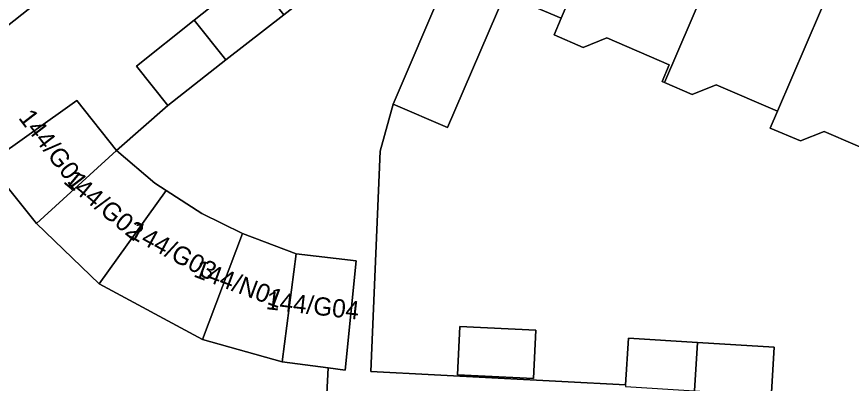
# Model space of a CAD drawing. Extents: x 162073 to 163043, y 381818 to 382561.
# Drawn here: x 162373.02 to 162418.89, y 382500.88 to 382521.02 of the extents above; entities that cross this region are included whole.
import ezdxf

# ---------------------------------------------------------------- set-up
doc = ezdxf.new("R2010")
doc.units = 0
for name, color, linetype in [('IMGEO_Erf', 7, 'Continuous'), ('IMGEO_Pand', 7, 'Continuous'), ('IMGEO_Pand_nummerreeks', 7, 'Continuous'), ('IMGEO_Voetpad_open', 7, 'Continuous')]:
    doc.layers.add(name, color=color, linetype=linetype)

msp = doc.modelspace()

# ---------------------------------------------------------------- linework, layer by layer
at = {"layer": 'IMGEO_Erf'}
for points in [[(162390.073, 382500.303), (162390.14, 382501.726), (162387.609, 382502.067), (162383.242, 382503.294), (162377.562, 382506.355), (162374.113, 382509.665), (162371.452, 382512.961), (162376.327, 382516.427), (162378.502, 382513.68), (162381.325, 382516.15), (162379.6, 382518.314), (162382.769, 382520.84), (162385.938, 382523.365), (162387.7, 382521.135), (162389.19, 382522.297), (162387.022, 382524.835), (162387.393, 382525.154), (162384.016, 382529.006), (162383.693, 382529.374), (162378.969, 382525.61), (162374.359, 382521.985), (162369.619, 382518.258)], [(162420.806, 382513.257), (162417.404, 382514.718), (162416.091, 382514.196), (162414.438, 382514.908), (162414.833, 382515.826), (162411.455, 382517.277), (162410.142, 382516.755), (162408.627, 382517.407), (162408.489, 382517.466), (162408.884, 382518.385), (162405.46, 382519.855), (162404.147, 382519.334), (162402.555, 382520.019), (162402.948, 382520.938), (162399.859, 382522.267), (162396.707, 382514.939), (162393.719, 382516.224), (162392.996, 382513.631), (162392.481, 382501.527), (162406.489, 382500.801), (162406.644, 382503.357), (162410.442, 382503.127), (162414.648, 382502.872), (162414.497, 382500.375)]]:
    msp.add_lwpolyline(points, dxfattribs=at)
msp.add_lwpolyline([(162401.426, 382501.149), (162397.246, 382501.35), (162397.374, 382503.996), (162401.554, 382503.794)], close=True, dxfattribs=at)
at = {"layer": 'IMGEO_Pand'}
for points in [[(162406.874, 382530.126), (162406.071, 382530.47), (162406.345, 382531.111), (162403.167, 382532.471), (162402.914, 382531.879), (162400.803, 382532.782), (162398.47, 382527.329), (162396.504, 382522.733), (162393.719, 382516.224), (162396.707, 382514.939), (162399.859, 382522.267), (162402.948, 382520.938)], [(162412.97, 382527.512), (162412.058, 382527.902), (162412.325, 382528.526), (162409.122, 382529.896), (162408.857, 382529.278), (162406.874, 382530.126), (162402.948, 382520.938), (162402.555, 382520.019), (162404.147, 382519.334), (162405.46, 382519.855), (162408.884, 382518.385), (162408.489, 382517.466), (162408.627, 382517.407)], [(162363.669, 382525.973), (162369.492, 382518.423), (162369.619, 382518.258), (162374.359, 382521.985), (162368.445, 382529.655)], [(162408.627, 382517.407), (162410.142, 382516.755), (162411.455, 382517.277), (162414.833, 382515.826), (162418.777, 382525), (162418.014, 382525.326), (162418.294, 382525.98), (162415.102, 382527.345), (162414.832, 382526.715), (162412.97, 382527.512)], [(162420.548, 382512.279), (162424.876, 382522.39), (162424.013, 382522.759), (162424.282, 382523.388), (162421.119, 382524.741), (162420.85, 382524.113), (162418.777, 382525), (162414.833, 382515.826), (162414.438, 382514.908), (162416.091, 382514.196), (162417.404, 382514.718), (162420.806, 382513.257), (162420.411, 382512.338)], [(162382.769, 382520.84), (162384.517, 382518.646), (162387.7, 382521.135), (162385.938, 382523.365)], [(162382.769, 382520.84), (162379.6, 382518.314), (162381.325, 382516.15), (162384.517, 382518.646)], [(162374.113, 382509.665), (162378.502, 382513.68), (162376.327, 382516.427), (162371.452, 382512.961)], [(162381.244, 382511.476), (162380.622, 382511.882), (162378.502, 382513.68), (162374.113, 382509.665), (162377.562, 382506.355)], [(162381.244, 382511.476), (162377.562, 382506.355), (162383.242, 382503.294), (162385.436, 382509.111), (162383.191, 382510.204)], [(162383.242, 382503.294), (162387.609, 382502.067), (162388.384, 382508.004), (162385.436, 382509.111)], [(162391.687, 382507.612), (162388.384, 382508.004), (162387.609, 382502.067), (162390.14, 382501.726), (162391.079, 382501.6)], [(162401.426, 382501.149), (162401.554, 382503.794), (162397.374, 382503.996), (162397.246, 382501.35)], [(162410.442, 382503.127), (162406.644, 382503.357), (162406.489, 382500.801), (162406.483, 382500.704), (162410.281, 382500.473)], [(162414.648, 382502.872), (162410.442, 382503.127), (162410.281, 382500.473), (162414.488, 382500.219), (162414.497, 382500.375)]]:
    msp.add_lwpolyline(points, close=True, dxfattribs=at)
at = {"layer": 'IMGEO_Voetpad_open'}
msp.add_lwpolyline([(162406.489, 382500.801), (162392.481, 382501.527), (162392.996, 382513.631), (162393.719, 382516.224), (162396.504, 382522.733), (162398.47, 382527.329), (162393.833, 382528.975), (162391.873, 382524.4), (162389.19, 382522.297), (162387.7, 382521.135), (162384.517, 382518.646), (162381.325, 382516.15), (162378.502, 382513.68), (162380.622, 382511.882), (162381.244, 382511.476), (162383.191, 382510.204), (162385.436, 382509.111), (162388.384, 382508.004), (162391.687, 382507.612), (162391.079, 382501.6), (162390.14, 382501.726), (162390.073, 382500.303)], dxfattribs=at)

# ---------------------------------------------------------------- texts
at = {"layer": 'IMGEO_Pand_nummerreeks'}
for s, rotation, p in [('144/G01', 307.5519, (162373.086, 382515.457)), ('144/G02', 320.3562, (162375.54, 382511.922)), ('144/G03', 331.5552, (162379.139, 382508.947)), ('144/N01', 339.5555, (162382.693, 382506.764)), ('144/G04', 353.4568, (162386.694, 382504.963))]:
    msp.add_text(s, height=1, rotation=rotation, dxfattribs=at).set_placement(p)

doc.saveas('drawing.dxf')
